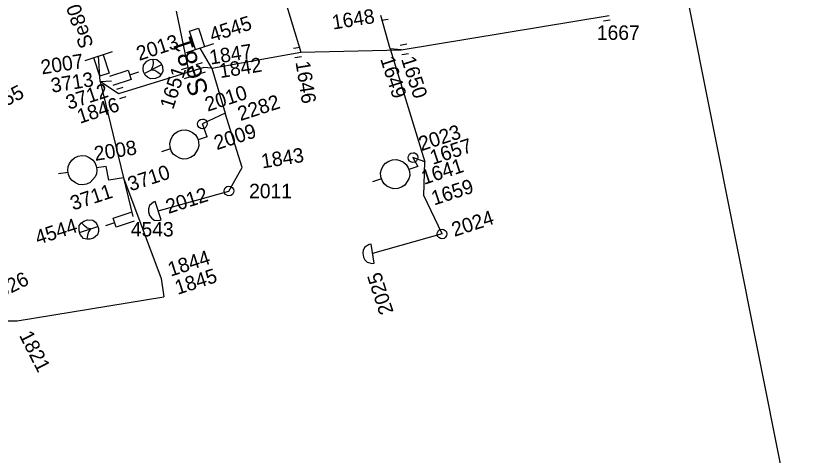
# Model space of a CAD drawing. Extents: x -535557 to -534097, y -1142175 to -1136716.
# Drawn here: x -534439.74 to -534399.09, y -1139633.14 to -1139610.3 of the extents above; entities that cross this region are included whole.
import ezdxf

# ---------------------------------------------------------------- set-up
doc = ezdxf.new("R2010")
doc.units = 0
doc.layers.add('Default', color=7, linetype='Continuous')
doc.layers.add('SS_SZDC', color=7, linetype='Continuous')

# ---------------------------------------------------------------- blocks, each defined once
blk = doc.blocks.new('POINT_DISPLAY')
at = {"layer": 'Default'}
blk.add_line((0, 0), (0, 0), dxfattribs=at)

msp = doc.modelspace()

# ---------------------------------------------------------------- linework, layer by layer
at = {"layer": 'SS_SZDC'}
for p, q in [((-534399.09, -1139638.01), (-534408.56, -1139590.44)), ((-534427.84, -1139602.53), (-534424.909, -1139612.19)), ((-534430.72, -1139613.239), (-534431.38, -1139610.059)), ((-534420.26, -1139612.02), (-534420.75, -1139610.28)), ((-534419.699, -1139612.069), (-534408.869, -1139610.29)), ((-534420.71, -1139610.526), (-534420.365, -1139610.472)), ((-534408.83, -1139610.536), (-534409.176, -1139610.591)), ((-534430.702, -1139611.109), (-534430.227, -1139610.952)), ((-534430.387, -1139612.058), (-534430.702, -1139611.109)), ((-534430.227, -1139610.952), (-534429.912, -1139611.901)), ((-534430.861, -1139612.216), (-534429.438, -1139611.743)), ((-534429.539, -1139613.03), (-534430.149, -1139611.979)), ((-534424.949, -1139611.943), (-534425.294, -1139611.997)), ((-534419.739, -1139611.823), (-534419.393, -1139611.768)), ((-534434.716, -1139612.178), (-534436.143, -1139612.641)), ((-534435.192, -1139612.332), (-534434.883, -1139613.283)), ((-534429.539, -1139613.03), (-534424.909, -1139612.19)), ((-534424.909, -1139612.19), (-534419.699, -1139612.069)), ((-534419.699, -1139612.069), (-534420.26, -1139612.02)), ((-534420.26, -1139612.02), (-534418.47, -1139617.899)), ((-534419.66, -1139612.316), (-534419.315, -1139612.262)), ((-534435.358, -1139613.438), (-534435.667, -1139612.487)), ((-534435.35, -1139613.709), (-534435.43, -1139612.409)), ((-534433.093, -1139612.872), (-534432.916, -1139612.669)), ((-534432.916, -1139612.669), (-534432.737, -1139612.579)), ((-534432.737, -1139612.579), (-534432.581, -1139612.555)), ((-534432.6, -1139612.958), (-534432.579, -1139612.779)), ((-534432.581, -1139612.555), (-534432.402, -1139612.576)), ((-534432.579, -1139612.779), (-534432.581, -1139612.555)), ((-534432.402, -1139612.576), (-534432.199, -1139612.753)), ((-534432.199, -1139612.753), (-534432.109, -1139612.932)), ((-534430.037, -1139612.752), (-534430.37, -1139612.86)), ((-534424.87, -1139612.436), (-534425.216, -1139612.491)), ((-534434.837, -1139613.442), (-534433.886, -1139613.133)), ((-534429.96, -1139612.989), (-534434.399, -1139614.36)), ((-534433.886, -1139613.133), (-534433.731, -1139613.608)), ((-534433.114, -1139613.051), (-534433.093, -1139612.872)), ((-534433.09, -1139613.207), (-534433.114, -1139613.051)), ((-534432.154, -1139612.843), (-534433.045, -1139613.296)), ((-534432.689, -1139613.115), (-534432.6, -1139612.958)), ((-534432.689, -1139613.115), (-534432.51, -1139613.136)), ((-534432.51, -1139613.136), (-534432.352, -1139613.224)), ((-534432.084, -1139613.2), (-534432.172, -1139613.357)), ((-534432.109, -1139612.932), (-534432.084, -1139613.2)), ((-534430.797, -1139613.002), (-534431.13, -1139613.11)), ((-534429.96, -1139612.989), (-534430.72, -1139613.239)), ((-534429.539, -1139613.03), (-534429.96, -1139612.989)), ((-534429.539, -1139613.03), (-534428.849, -1139615.37)), ((-534434.883, -1139613.283), (-534435.358, -1139613.438)), ((-534433.731, -1139613.608), (-534434.682, -1139613.917)), ((-534433.808, -1139613.37), (-534433.333, -1139613.216)), ((-534433, -1139613.386), (-534433.09, -1139613.207)), ((-534432.887, -1139613.497), (-534433, -1139613.386)), ((-534432.73, -1139613.585), (-534432.887, -1139613.497)), ((-534432.462, -1139613.56), (-534432.73, -1139613.585)), ((-534432.283, -1139613.47), (-534432.462, -1139613.56)), ((-534432.352, -1139613.224), (-534432.172, -1139613.357)), ((-534432.172, -1139613.357), (-534432.283, -1139613.47)), ((-534430.642, -1139613.477), (-534430.975, -1139613.585)), ((-534429.882, -1139613.227), (-534430.215, -1139613.335)), ((-534435.35, -1139613.709), (-534434.76, -1139613.68)), ((-534434.399, -1139614.36), (-534435.35, -1139613.709)), ((-534435.35, -1139613.709), (-534434.14, -1139618.729)), ((-534434.477, -1139614.122), (-534434.144, -1139614.014)), ((-534434.322, -1139614.597), (-534433.989, -1139614.489)), ((-534428.849, -1139615.37), (-534430.029, -1139615.92)), ((-534427.96, -1139618.18), (-534428.849, -1139615.37)), ((-534430.279, -1139615.916), (-534430.268, -1139615.846)), ((-534430.261, -1139616.026), (-534430.279, -1139615.916)), ((-534430.268, -1139615.846), (-534430.217, -1139615.747)), ((-534430.202, -1139616.107), (-534430.261, -1139616.026)), ((-534430.217, -1139615.747), (-534430.136, -1139615.688)), ((-534430.136, -1139615.688), (-534430.026, -1139615.67)), ((-534429.779, -1139616.6), (-534430.029, -1139615.92)), ((-534430.026, -1139615.67), (-534429.956, -1139615.681)), ((-534429.956, -1139615.681), (-534429.857, -1139615.732)), ((-534429.857, -1139615.732), (-534429.798, -1139615.813)), ((-534429.791, -1139615.993), (-534429.842, -1139616.092)), ((-534429.798, -1139615.813), (-534429.78, -1139615.923)), ((-534429.78, -1139615.923), (-534429.791, -1139615.993)), ((-534431.582, -1139616.554), (-534431.47, -1139616.413)), ((-534431.47, -1139616.413), (-534431.295, -1139616.303)), ((-534431.295, -1139616.303), (-534431.105, -1139616.242)), ((-534431.105, -1139616.242), (-534430.899, -1139616.227)), ((-534430.899, -1139616.227), (-534430.726, -1139616.276)), ((-534430.726, -1139616.276), (-534430.537, -1139616.372)), ((-534430.537, -1139616.372), (-534430.395, -1139616.484)), ((-534430.103, -1139616.158), (-534430.202, -1139616.107)), ((-534430.033, -1139616.169), (-534430.103, -1139616.158)), ((-534429.923, -1139616.151), (-534430.033, -1139616.169)), ((-534429.842, -1139616.092), (-534429.923, -1139616.151)), ((-534431.727, -1139616.917), (-534431.678, -1139616.743)), ((-534431.678, -1139616.743), (-534431.582, -1139616.554)), ((-534430.395, -1139616.484), (-534430.286, -1139616.659)), ((-534430.286, -1139616.659), (-534430.255, -1139616.754)), ((-534429.779, -1139616.6), (-534430.255, -1139616.754)), ((-534430.255, -1139616.754), (-534430.224, -1139616.849)), ((-534430.224, -1139616.849), (-534430.21, -1139617.055)), ((-534431.682, -1139617.218), (-534432.157, -1139617.372)), ((-534431.713, -1139617.122), (-534431.727, -1139616.917)), ((-534431.651, -1139617.313), (-534431.713, -1139617.122)), ((-534430.259, -1139617.228), (-534430.467, -1139617.559)), ((-534430.21, -1139617.055), (-534430.259, -1139617.228)), ((-534436.68, -1139617.681), (-534436.49, -1139617.6)), ((-534436.49, -1139617.6), (-534436.293, -1139617.569)), ((-534436.293, -1139617.569), (-534436.087, -1139617.587)), ((-534436.087, -1139617.587), (-534435.924, -1139617.662)), ((-534435.924, -1139617.662), (-534435.752, -1139617.787)), ((-534431.541, -1139617.487), (-534431.651, -1139617.313)), ((-534431.4, -1139617.599), (-534431.541, -1139617.487)), ((-534431.211, -1139617.695), (-534431.4, -1139617.599)), ((-534430.641, -1139617.668), (-534430.832, -1139617.73)), ((-534430.467, -1139617.559), (-534430.641, -1139617.668)), ((-534419.329, -1139617.666), (-534419.318, -1139617.596)), ((-534419.311, -1139617.776), (-534419.329, -1139617.666)), ((-534419.318, -1139617.596), (-534419.267, -1139617.497)), ((-534419.267, -1139617.497), (-534419.186, -1139617.438)), ((-534419.186, -1139617.438), (-534419.076, -1139617.42)), ((-534418.47, -1139617.899), (-534419.079, -1139617.67)), ((-534419.079, -1139617.67), (-534418.819, -1139618.139)), ((-534419.076, -1139617.42), (-534419.006, -1139617.431)), ((-534419.006, -1139617.431), (-534418.907, -1139617.482)), ((-534418.907, -1139617.482), (-534418.848, -1139617.563)), ((-534418.848, -1139617.563), (-534418.83, -1139617.673)), ((-534418.83, -1139617.673), (-534418.841, -1139617.743)), ((-534437.012, -1139618.138), (-534436.937, -1139617.974)), ((-534436.937, -1139617.974), (-534436.812, -1139617.803)), ((-534436.812, -1139617.803), (-534436.68, -1139617.681)), ((-534435.752, -1139617.787), (-534435.63, -1139617.919)), ((-534435.63, -1139617.919), (-534435.549, -1139618.109)), ((-534431.037, -1139617.744), (-534431.211, -1139617.695)), ((-534430.832, -1139617.73), (-534431.037, -1139617.744)), ((-534420.622, -1139618.106), (-534420.511, -1139617.964)), ((-534420.511, -1139617.964), (-534420.337, -1139617.853)), ((-534420.337, -1139617.853), (-534420.147, -1139617.79)), ((-534420.147, -1139617.79), (-534419.942, -1139617.775)), ((-534419.942, -1139617.775), (-534419.768, -1139617.822)), ((-534419.768, -1139617.822), (-534419.578, -1139617.917)), ((-534419.578, -1139617.917), (-534419.436, -1139618.028)), ((-534419.436, -1139618.028), (-534419.326, -1139618.202)), ((-534419.252, -1139617.857), (-534419.311, -1139617.776)), ((-534419.153, -1139617.908), (-534419.252, -1139617.857)), ((-534419.083, -1139617.919), (-534419.153, -1139617.908)), ((-534418.973, -1139617.901), (-534419.083, -1139617.919)), ((-534418.892, -1139617.842), (-534418.973, -1139617.901)), ((-534418.841, -1139617.743), (-534418.892, -1139617.842)), ((-534418.52, -1139619.639), (-534418.47, -1139617.899)), ((-534437.015, -1139618.442), (-534437.509, -1139618.521)), ((-534437.031, -1139618.344), (-534437.012, -1139618.138)), ((-534436.999, -1139618.541), (-534437.031, -1139618.344)), ((-534435.549, -1139618.109), (-534435.533, -1139618.208)), ((-534435.518, -1139618.306), (-534435.536, -1139618.512)), ((-534435.039, -1139618.129), (-534435.533, -1139618.208)), ((-534435.533, -1139618.208), (-534435.518, -1139618.306)), ((-534434.89, -1139618.84), (-534435.039, -1139618.129)), ((-534428.649, -1139619.409), (-534427.96, -1139618.18)), ((-534420.765, -1139618.47), (-534420.717, -1139618.296)), ((-534420.749, -1139618.675), (-534420.765, -1139618.47)), ((-534420.717, -1139618.296), (-534420.622, -1139618.106)), ((-534419.326, -1139618.202), (-534419.294, -1139618.297)), ((-534418.819, -1139618.139), (-534419.294, -1139618.297)), ((-534419.294, -1139618.297), (-534419.262, -1139618.392)), ((-534419.262, -1139618.392), (-534419.247, -1139618.598)), ((-534436.919, -1139618.731), (-534436.999, -1139618.541)), ((-534436.796, -1139618.863), (-534436.919, -1139618.731)), ((-534436.625, -1139618.988), (-534436.796, -1139618.863)), ((-534435.611, -1139618.676), (-534435.868, -1139618.969)), ((-534435.536, -1139618.512), (-534435.611, -1139618.676)), ((-534434.14, -1139618.729), (-534434.89, -1139618.84)), ((-534434.14, -1139618.729), (-534433.649, -1139620.739)), ((-534434.14, -1139618.729), (-534432.17, -1139623.95)), ((-534420.718, -1139618.77), (-534421.192, -1139618.928)), ((-534420.686, -1139618.865), (-534420.749, -1139618.675)), ((-534420.575, -1139619.039), (-534420.686, -1139618.865)), ((-534419.294, -1139618.771), (-534419.5, -1139619.103)), ((-534419.247, -1139618.598), (-534419.294, -1139618.771)), ((-534436.461, -1139619.063), (-534436.625, -1139618.988)), ((-534436.256, -1139619.081), (-534436.461, -1139619.063)), ((-534436.058, -1139619.05), (-534436.256, -1139619.081)), ((-534435.868, -1139618.969), (-534436.058, -1139619.05)), ((-534428.888, -1139619.336), (-534428.837, -1139619.237)), ((-534428.837, -1139619.237), (-534428.756, -1139619.178)), ((-534428.756, -1139619.178), (-534428.646, -1139619.16)), ((-534428.646, -1139619.16), (-534428.576, -1139619.171)), ((-534428.576, -1139619.171), (-534428.477, -1139619.222)), ((-534428.477, -1139619.222), (-534428.418, -1139619.303)), ((-534420.433, -1139619.15), (-534420.575, -1139619.039)), ((-534420.244, -1139619.245), (-534420.433, -1139619.15)), ((-534420.07, -1139619.292), (-534420.244, -1139619.245)), ((-534419.864, -1139619.277), (-534420.07, -1139619.292)), ((-534419.674, -1139619.214), (-534419.864, -1139619.277)), ((-534419.5, -1139619.103), (-534419.674, -1139619.214)), ((-534432.329, -1139620.43), (-534428.649, -1139619.409)), ((-534428.899, -1139619.406), (-534428.888, -1139619.336)), ((-534428.881, -1139619.516), (-534428.899, -1139619.406)), ((-534428.822, -1139619.597), (-534428.881, -1139619.516)), ((-534428.723, -1139619.648), (-534428.822, -1139619.597)), ((-534428.653, -1139619.659), (-534428.723, -1139619.648)), ((-534428.543, -1139619.641), (-534428.653, -1139619.659)), ((-534428.462, -1139619.582), (-534428.543, -1139619.641)), ((-534428.411, -1139619.483), (-534428.462, -1139619.582)), ((-534428.418, -1139619.303), (-534428.4, -1139619.413)), ((-534428.4, -1139619.413), (-534428.411, -1139619.483)), ((-534417.569, -1139621.639), (-534418.52, -1139619.639)), ((-534432.579, -1139619.985), (-534432.786, -1139620.157)), ((-534432.484, -1139619.954), (-534432.579, -1139619.985)), ((-534432.175, -1139620.905), (-534432.484, -1139619.954)), ((-534434.677, -1139620.817), (-534433.728, -1139620.502)), ((-534432.835, -1139620.331), (-534432.836, -1139620.489)), ((-534432.836, -1139620.489), (-534432.774, -1139620.679)), ((-534432.786, -1139620.157), (-534432.835, -1139620.331)), ((-534436.192, -1139620.967), (-534436.002, -1139620.903)), ((-534436.002, -1139620.903), (-534435.733, -1139620.92)), ((-534435.733, -1139620.92), (-534435.591, -1139621.03)), ((-534434.52, -1139621.292), (-534434.677, -1139620.817)), ((-534432.774, -1139620.679), (-534432.68, -1139620.806)), ((-534432.68, -1139620.806), (-534432.539, -1139620.918)), ((-534432.539, -1139620.918), (-534432.27, -1139620.936)), ((-534432.27, -1139620.936), (-534432.175, -1139620.905)), ((-534436.446, -1139621.472), (-534436.429, -1139621.203)), ((-534436.429, -1139621.203), (-534436.319, -1139621.061)), ((-534436.414, -1139621.567), (-534435.465, -1139621.252)), ((-534436.319, -1139621.061), (-534436.192, -1139620.967)), ((-534436.161, -1139621.22), (-534436.319, -1139621.061)), ((-534436.018, -1139621.33), (-534436.161, -1139621.22)), ((-534435.845, -1139621.378), (-534436.018, -1139621.33)), ((-534435.591, -1139621.03), (-534435.497, -1139621.157)), ((-534435.497, -1139621.157), (-534435.433, -1139621.347)), ((-534434.599, -1139621.055), (-534435.073, -1139621.212)), ((-534433.571, -1139620.977), (-534434.52, -1139621.292)), ((-534436.382, -1139621.662), (-534436.446, -1139621.472)), ((-534436.209, -1139621.868), (-534436.382, -1139621.662)), ((-534436.003, -1139621.694), (-534436.035, -1139621.915)), ((-534435.955, -1139621.52), (-534436.003, -1139621.694)), ((-534435.845, -1139621.378), (-534435.955, -1139621.52)), ((-534435.481, -1139621.679), (-534435.687, -1139621.852)), ((-534435.434, -1139621.505), (-534435.481, -1139621.679)), ((-534435.433, -1139621.347), (-534435.434, -1139621.505)), ((-534417.569, -1139621.639), (-534421.18, -1139622.659)), ((-534417.819, -1139621.636), (-534417.808, -1139621.566)), ((-534417.801, -1139621.746), (-534417.819, -1139621.636)), ((-534417.808, -1139621.566), (-534417.757, -1139621.467)), ((-534417.757, -1139621.467), (-534417.676, -1139621.408)), ((-534417.676, -1139621.408), (-534417.566, -1139621.39)), ((-534417.566, -1139621.39), (-534417.496, -1139621.401)), ((-534417.496, -1139621.401), (-534417.397, -1139621.452)), ((-534417.397, -1139621.452), (-534417.338, -1139621.533)), ((-534417.331, -1139621.713), (-534417.382, -1139621.812)), ((-534417.338, -1139621.533), (-534417.32, -1139621.643)), ((-534417.32, -1139621.643), (-534417.331, -1139621.713)), ((-534436.035, -1139621.915), (-534436.209, -1139621.868)), ((-534435.877, -1139621.916), (-534436.035, -1139621.915)), ((-534435.687, -1139621.852), (-534435.877, -1139621.916)), ((-534417.742, -1139621.827), (-534417.801, -1139621.746)), ((-534417.643, -1139621.878), (-534417.742, -1139621.827)), ((-534417.573, -1139621.889), (-534417.643, -1139621.878)), ((-534417.463, -1139621.871), (-534417.573, -1139621.889)), ((-534417.382, -1139621.812), (-534417.463, -1139621.871)), ((-534421.664, -1139622.486), (-534421.689, -1139622.642)), ((-534421.59, -1139622.322), (-534421.664, -1139622.486)), ((-534421.36, -1139622.182), (-534421.59, -1139622.322)), ((-534421.261, -1139622.166), (-534421.36, -1139622.182)), ((-534421.098, -1139623.153), (-534421.261, -1139622.166)), ((-534421.689, -1139622.642), (-534421.657, -1139622.84)), ((-534421.657, -1139622.84), (-534421.583, -1139622.979)), ((-534421.583, -1139622.979), (-534421.46, -1139623.111)), ((-534421.46, -1139623.111), (-534421.197, -1139623.169)), ((-534421.197, -1139623.169), (-534421.098, -1139623.153)), ((-534432.17, -1139623.95), (-534432.039, -1139624.909)), ((-534439.67, -1139626.159), (-534432.039, -1139624.909)), ((-534441.26, -1139626.149), (-534439.67, -1139626.159))]:
    msp.add_line(p, q, dxfattribs=at)

# ---------------------------------------------------------------- block references
for p in [(-534430.149, -1139611.979), (-534424.909, -1139612.19), (-534420.26, -1139612.02), (-534419.699, -1139612.069), (-534435.43, -1139612.409), (-534432.6, -1139613.069), (-534429.96, -1139612.989), (-534429.539, -1139613.03), (-534430.72, -1139613.239), (-534435.35, -1139613.709), (-534434.76, -1139613.68), (-534434.399, -1139614.36), (-534428.849, -1139615.37), (-534430.029, -1139615.92), (-534430.029, -1139615.92), (-534429.779, -1139616.6), (-534419.079, -1139617.67), (-534419.079, -1139617.67), (-534418.47, -1139617.899), (-534435.039, -1139618.129), (-534427.96, -1139618.18), (-534418.819, -1139618.139), (-534434.89, -1139618.84), (-534434.14, -1139618.729), (-534428.649, -1139619.409), (-534428.649, -1139619.409), (-534418.52, -1139619.639), (-534432.329, -1139620.43), (-534433.649, -1139620.739), (-534435.939, -1139621.409), (-534417.569, -1139621.639), (-534417.569, -1139621.639), (-534421.18, -1139622.659), (-534432.17, -1139623.95), (-534432.039, -1139624.909), (-534439.67, -1139626.159)]:
    msp.add_blockref('POINT_DISPLAY', p, dxfattribs=at)

# ---------------------------------------------------------------- texts
for s, height, rotation, p in [('Se80', 0.75, 108.3756, (-534435.679, -1139611.845)), ('1648', 0.75, 9, (-534423.231, -1139611.02)), ('4545', 0.75, 18, (-534429.515, -1139611.679)), ('2013', 0.75, 18, (-534433.316, -1139612.648)), ('Se81', 1, 108.3757, (-534429.69, -1139614.277)), ('1847', 0.75, 9, (-534429.604, -1139612.842)), ('2007', 0.75, 9, (-534438.372, -1139613.353)), ('1842', 0.75, 9, (-534429.097, -1139613.543)), ('1646', 0.75, 279, (-534425.19, -1139612.708)), ('1649', 0.75, 288, (-534420.791, -1139612.547)), ('1650', 0.75, 288, (-534419.706, -1139612.547)), ('1651', 0.75, 72, (-534431.554, -1139615.209)), ('3713', 0.75, 9, (-534437.85, -1139614.303)), ('1955', 0.75, 27, (-534441.222, -1139615.53)), ('3712', 0.75, 18, (-534436.984, -1139615.192)), ('2010', 0.75, 18, (-534429.756, -1139615.289)), ('2282', 0.75, 18, (-534428.053, -1139615.777)), ('1846', 0.75, 18, (-534436.402, -1139615.916)), ('2009', 0.75, 18, (-534429.281, -1139617.285)), ('2023', 0.75, 18, (-534418.641, -1139617.338)), ('2008', 0.75, 9, (-534435.602, -1139617.844)), ('1657', 0.75, 18, (-534418.052, -1139618.048)), ('1843', 0.75, 9, (-534426.911, -1139618.236)), ('3710', 0.75, 18, (-534433.769, -1139619.428)), ('1641', 0.75, 18, (-534418.503, -1139619.088)), ('1659', 0.75, 18, (-534417.983, -1139620.162)), ('3711', 0.75, 18, (-534436.758, -1139620.424)), ('2012', 0.75, 18, (-534431.792, -1139620.6)), ('2024', 0.75, 18, (-534416.926, -1139621.79)), ('4544', 0.75, 18, (-534438.587, -1139622.21)), ('1844', 0.75, 18, (-534431.682, -1139623.862)), ('2026', 0.75, 27, (-534440.972, -1139625.24)), ('1845', 0.75, 18, (-534431.319, -1139624.807)), ('2025', 0.75, 108, (-534420.079, -1139625.688)), ('1821', 0.75, 297, (-534439.577, -1139626.903))]:
    msp.add_text(s, height=height, rotation=rotation, dxfattribs=at).set_placement(p)
for s, p in [('1667', (-534409.518, -1139611.554)), ('2011', (-534427.6, -1139619.781)), ('4543', (-534433.755, -1139621.769))]:
    msp.add_text(s, height=0.75, dxfattribs=at).set_placement(p)

doc.saveas('drawing.dxf')
